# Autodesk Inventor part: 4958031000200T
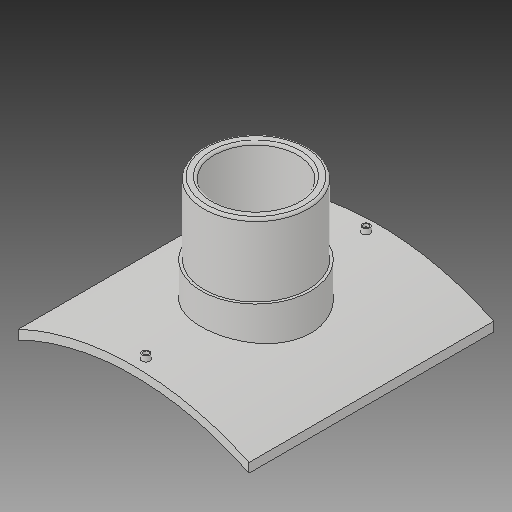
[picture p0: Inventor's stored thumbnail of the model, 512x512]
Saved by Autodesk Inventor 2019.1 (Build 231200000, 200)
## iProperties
Created: 2017-10
Part Number: 4958031000200T
Material: Generic
Description: PLASSON BRANCH SADDLE 1000x200
Document SubType Name: Modeling
Designer: KIM
Mass: 2754.05 g
Surface Area: 3037.44 cm^2
Volume: 2754.05 cm^3
Density: 1 g/cm^3
Appearance: Default
Author: KIM
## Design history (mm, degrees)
derived "495803.ipt"
feature "Solid1::495803.ipt"
tag "TaggingFeature1"
body "Solid1"
other parameters: "d1" = 16, "d2" = 443, "d4" = 0, "d12" = 525.6, "d13" = 14, "d14" = 211.5, "d16" = 5 deg, "d18" = 4, "d19" = 14, "d20" = 0, "d21" = 3, "d22" = 0, "d23" = 714, "d25" = 16, "d28" = 0, "d29" = 9.6, "d31" = 0, "d32" = 99, "d33" = 0, "d37" = 138.6, "d38" = 0, "d39" = 5, "B_" = 443, "H_" = 198, "x_" = 16, "D_" = 16
